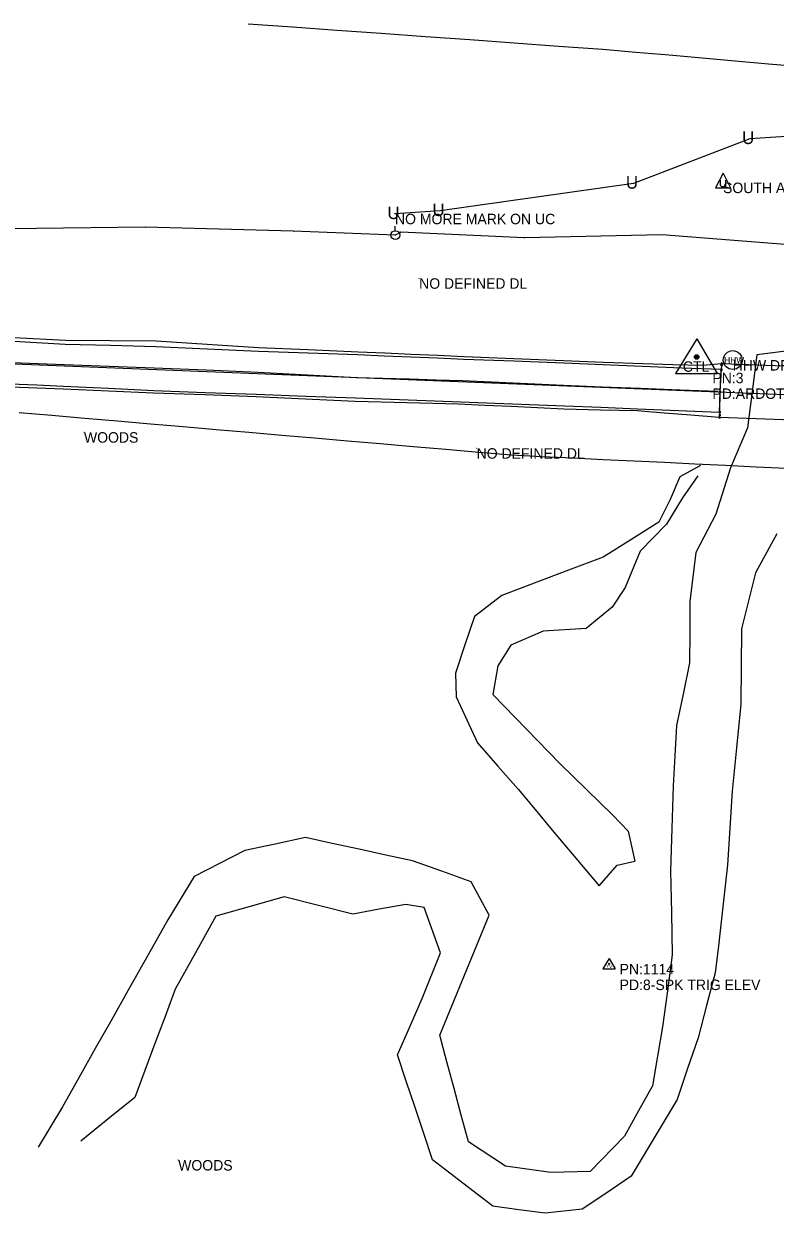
# Model space of a CAD drawing. Extents: x 1138803 to 1169983, y 1655906 to 1658226.
# Drawn here: x 1141218 to 1141577, y 1657244 to 1657812 of the extents above; entities that cross this region are included whole.
import ezdxf

# ---------------------------------------------------------------- set-up
doc = ezdxf.new("R2010")
doc.units = 0
for name, color, linetype in [('Default', 7, 'Continuous'), ('S_BRIDGE', 7, 'Continuous'), ('S_DITCHLINE', 7, 'Continuous'), ('S_EDGE_PAVEMENT', 7, 'Continuous'), ('S_EXISTING_ALIGNMENT', 7, 'Continuous'), ('S_FIBER_OPTIC_CABLE', 7, 'Continuous'), ('S_HIST_HIGH_WATER', 7, 'Continuous'), ('S_HIST_HIGH_WATER_ANNOT', 7, 'Continuous'), ('S_MSC_PT_SYM', 7, 'Continuous'), ('S_PAVEMENT_CROWN', 7, 'Continuous'), ('S_PRIMARY_CTL', 7, 'Continuous'), ('S_PRIMARY_CTL_ANNOT', 7, 'Continuous'), ('S_SECONDARY_CTL', 7, 'Continuous'), ('S_SECONDARY_CTL_ANNOT', 7, 'Continuous'), ('S_SHOULDER', 7, 'Continuous'), ('S_STR_PT_SYM', 7, 'Continuous'), ('S_STREAM', 7, 'Continuous'), ('S_SURVEY_TEXT_ANNOT', 7, 'Continuous'), ('S_TREE', 7, 'Continuous'), ('S_UNDERGROUND_CABLE', 7, 'Continuous'), ('S_UTILITY_POLE', 7, 'Continuous'), ('S_UTILITY_POLE_ANNOT', 7, 'Continuous'), ('S_UTL_PT_SYM', 7, 'Continuous')]:
    doc.layers.add(name, color=color, linetype=linetype)

msp = doc.modelspace()

# ---------------------------------------------------------------- linework, layer by layer
at = {"layer": 'S_BRIDGE'}
for p, q in [((1141550.51, 1657636.42), (1141551.05, 1657647.03)), ((1141551.05, 1657647.03), (1141551.2, 1657649.23)), ((1141551.2, 1657649.23), (1141551.33, 1657650)), ((1141551.33, 1657650), (1141657.88, 1657645.9)), ((1141550.32, 1657626.72), (1141550.51, 1657636.42)), ((1141550.22, 1657624.21), (1141550.27, 1657625.35)), ((1141656.97, 1657620.11), (1141550.22, 1657624.21)), ((1141550.27, 1657625.35), (1141550.32, 1657626.72))]:
    msp.add_line(p, q, dxfattribs=at)
at = {"layer": 'S_DITCHLINE'}
for points in [[(1141541.04, 1657601.27), (1141531.25, 1657595.88), (1141526.63, 1657585.07), (1141521.22, 1657574.19), (1141507.88, 1657565.88), (1141494.54, 1657557.57), (1141478.07, 1657551.36), (1141461.6, 1657545.15), (1141446.26, 1657539.17), (1141433.2, 1657529.16), (1141428.61, 1657515.63), (1141424.02, 1657502.1), (1141424.42, 1657490.82), (1141434.58, 1657468.85), (1141444.28, 1657457.86), (1141453.98, 1657446.86), (1141462.12, 1657437.05), (1141470.25, 1657427.24), (1141481.5, 1657413.95), (1141492.75, 1657400.66), (1141501.28, 1657410.54), (1141509.7, 1657412.4)], [(1141539.75, 1657596.34), (1141532.41, 1657585.9), (1141524.85, 1657573.36), (1141512.28, 1657560.34), (1141505.08, 1657543.03), (1141498.82, 1657533.6), (1141486.53, 1657523.47), (1141465.99, 1657522.16), (1141450.49, 1657515.58), (1141444.25, 1657505.75), (1141441.92, 1657491.99), (1141457.97, 1657475.42), (1141474.02, 1657458.85), (1141486.63, 1657446.6), (1141499.23, 1657434.34), (1141506.52, 1657426.83), (1141509.71, 1657412.45)]]:
    msp.add_lwpolyline(points, dxfattribs=at)
at = {"layer": 'S_EDGE_PAVEMENT'}
for points in [[(1141550.85, 1657647.04), (1141532.15, 1657647.74), (1141513.44, 1657648.45), (1141494.6, 1657649.28), (1141475.75, 1657650.11), (1141451.94, 1657651.01), (1141428.12, 1657651.91), (1141415.44, 1657652.45), (1141402.76, 1657652.98), (1141390.08, 1657653.52), (1141377.4, 1657654.06), (1141353.66, 1657654.85), (1141329.92, 1657655.65), (1141305.44, 1657656.78), (1141280.95, 1657657.91), (1141259.32, 1657658.49), (1141237.68, 1657659.07), (1141213.11, 1657660.44)], [(1141550.85, 1657647.04), (1141550.33, 1657636.66), (1141550.03, 1657626.61), (1141530.53, 1657627.42), (1141511.03, 1657628.23), (1141493.55, 1657628.95), (1141476.07, 1657629.67), (1141451.31, 1657630.56), (1141426.54, 1657631.46), (1141413.99, 1657631.95), (1141401.44, 1657632.44), (1141388.89, 1657632.94), (1141376.34, 1657633.43), (1141352.59, 1657634.27), (1141328.84, 1657635.11), (1141304.45, 1657636.02), (1141280.05, 1657636.93), (1141258.42, 1657638), (1141236.8, 1657639.06), (1141224.13, 1657639.55), (1141211.47, 1657640.03)]]:
    msp.add_lwpolyline(points, dxfattribs=at)
at = {"layer": 'S_EXISTING_ALIGNMENT'}
msp.add_line((1140481.53, 1657679.14), (1142022.15, 1657617.46), dxfattribs=at)
at = {"layer": 'S_FIBER_OPTIC_CABLE'}
for p, q in [((1141275.94, 1657715.01), (1141210.99, 1657714.26)), ((1141346.62, 1657713.17), (1141275.94, 1657715.01)), ((1141395.33, 1657711.21), (1141346.62, 1657713.17)), ((1141397.9, 1657712.62), (1141395.33, 1657711.21)), ((1141457.09, 1657709.94), (1141397.9, 1657712.62)), ((1141522.77, 1657711.39), (1141457.09, 1657709.94)), ((1141628.93, 1657703.02), (1141522.77, 1657711.39))]:
    msp.add_line(p, q, dxfattribs=at)
at = {"layer": 'S_HIST_HIGH_WATER'}
msp.add_circle((1141556.45, 1657651.6), 4.5, dxfattribs=at)
at = {"layer": 'S_MSC_PT_SYM'}
for points in [[(1141395.17, 1657721.42), (1141395.17, 1657721.47), (1141395.17, 1657721.42), (1141395.12, 1657721.42), (1141395.17, 1657721.42), (1141395.17, 1657721.37), (1141395.17, 1657721.42), (1141395.22, 1657721.42)], [(1141406.72, 1657690.63), (1141406.72, 1657690.68), (1141406.72, 1657690.63), (1141406.67, 1657690.63), (1141406.72, 1657690.63), (1141406.72, 1657690.58), (1141406.72, 1657690.63), (1141406.77, 1657690.63)], [(1141246.64, 1657617.17), (1141246.64, 1657617.22), (1141246.64, 1657617.17), (1141246.59, 1657617.17), (1141246.64, 1657617.17), (1141246.64, 1657617.12), (1141246.64, 1657617.17), (1141246.69, 1657617.17)], [(1141434.17, 1657609.53), (1141434.17, 1657609.58), (1141434.17, 1657609.53), (1141434.12, 1657609.53), (1141434.17, 1657609.53), (1141434.17, 1657609.48), (1141434.17, 1657609.53), (1141434.22, 1657609.53)], [(1141291.64, 1657269.82), (1141291.64, 1657269.87), (1141291.64, 1657269.82), (1141291.59, 1657269.82), (1141291.64, 1657269.82), (1141291.64, 1657269.77), (1141291.64, 1657269.82), (1141291.69, 1657269.82)]]:
    msp.add_lwpolyline(points, dxfattribs=at)
at = {"layer": 'S_PAVEMENT_CROWN'}
msp.add_lwpolyline([(1141549.45, 1657636.6), (1141531.28, 1657637.31), (1141512.38, 1657638.04), (1141494, 1657638.73), (1141475.62, 1657639.42), (1141451.54, 1657640.54), (1141427.46, 1657641.65), (1141414.78, 1657642.04), (1141402.11, 1657642.42), (1141389.44, 1657642.8), (1141376.77, 1657643.18), (1141353.34, 1657644.42), (1141329.91, 1657645.66), (1141305.07, 1657646.7), (1141280.23, 1657647.74), (1141258.68, 1657648.53), (1141237.14, 1657649.33), (1141212.32, 1657650.33)], dxfattribs=at)
at = {"layer": 'S_PRIMARY_CTL'}
for p, q in [((1141539.25, 1657661.76), (1141529.21, 1657645.25)), ((1141539.25, 1657661.76), (1141549.07, 1657645.25)), ((1141529.21, 1657645.25), (1141549.07, 1657645.25))]:
    msp.add_line(p, q, dxfattribs=at)
for radius in [1.04, 0.609, 0.344]:
    msp.add_circle((1141539.25, 1657653.06), radius, dxfattribs=at)
at = {"layer": 'S_SECONDARY_CTL'}
for p, q in [((1141497.46, 1657366.05), (1141494.45, 1657361.1)), ((1141497.46, 1657366.05), (1141500.4, 1657361.1)), ((1141494.45, 1657361.1), (1141500.4, 1657361.1))]:
    msp.add_line(p, q, dxfattribs=at)
for radius in [0.311, 0.183, 0.103]:
    msp.add_circle((1141497.46, 1657363.44), radius, dxfattribs=at)
at = {"layer": 'S_SHOULDER'}
for points in [[(1141551.28, 1657649.82), (1141542.03, 1657648.94), (1141527.89, 1657649.37), (1141513.74, 1657649.8), (1141494.74, 1657650.5), (1141475.73, 1657651.2), (1141452, 1657652.17), (1141428.27, 1657653.15), (1141415.61, 1657653.71), (1141402.94, 1657654.27), (1141390.28, 1657654.83), (1141377.62, 1657655.4), (1141353.78, 1657656.43), (1141329.94, 1657657.45), (1141305.51, 1657659.04), (1141281.08, 1657660.62), (1141259.48, 1657660.76), (1141237.88, 1657660.9), (1141213.1, 1657662.14)], [(1141550.2, 1657626.27), (1141550.02, 1657625.04), (1141550.04, 1657624.21), (1141536.51, 1657625.26), (1141523.67, 1657626.28), (1141510.84, 1657627.3), (1141493.35, 1657627.74), (1141475.86, 1657628.19), (1141463.29, 1657628.78), (1141450.72, 1657629.37), (1141438.15, 1657629.96), (1141425.58, 1657630.56), (1141400.86, 1657631.18), (1141376.14, 1657631.79), (1141352.52, 1657632.91), (1141328.89, 1657634.03), (1141304.37, 1657634.93), (1141279.86, 1657635.83), (1141258.38, 1657636.77), (1141236.89, 1657637.71), (1141224.31, 1657638.17), (1141211.72, 1657638.64)]]:
    msp.add_lwpolyline(points, dxfattribs=at)
at = {"layer": 'S_STR_PT_SYM'}
for points in [[(1141551.05, 1657647.03), (1141551.05, 1657647.53), (1141551.05, 1657647.03), (1141550.55, 1657647.03), (1141551.05, 1657647.03), (1141551.05, 1657646.53), (1141551.05, 1657647.03), (1141551.55, 1657647.03)], [(1141551.2, 1657649.23), (1141551.2, 1657649.73), (1141551.2, 1657649.23), (1141550.7, 1657649.23), (1141551.2, 1657649.23), (1141551.2, 1657648.73), (1141551.2, 1657649.23), (1141551.7, 1657649.23)], [(1141551.33, 1657650), (1141551.33, 1657650.5), (1141551.33, 1657650), (1141550.83, 1657650), (1141551.33, 1657650), (1141551.33, 1657649.5), (1141551.33, 1657650), (1141551.83, 1657650)], [(1141550.51, 1657636.42), (1141550.51, 1657636.92), (1141550.51, 1657636.42), (1141550.01, 1657636.42), (1141550.51, 1657636.42), (1141550.51, 1657635.92), (1141550.51, 1657636.42), (1141551.01, 1657636.42)], [(1141550.22, 1657624.21), (1141550.22, 1657624.71), (1141550.22, 1657624.21), (1141549.72, 1657624.21), (1141550.22, 1657624.21), (1141550.22, 1657623.71), (1141550.22, 1657624.21), (1141550.72, 1657624.21)], [(1141550.27, 1657625.35), (1141550.27, 1657625.85), (1141550.27, 1657625.35), (1141549.77, 1657625.35), (1141550.27, 1657625.35), (1141550.27, 1657624.85), (1141550.27, 1657625.35), (1141550.77, 1657625.35)], [(1141550.32, 1657626.72), (1141550.32, 1657627.22), (1141550.32, 1657626.72), (1141549.82, 1657626.72), (1141550.32, 1657626.72), (1141550.32, 1657626.22), (1141550.32, 1657626.72), (1141550.82, 1657626.72)]]:
    msp.add_lwpolyline(points, dxfattribs=at)
at = {"layer": 'S_STREAM'}
for points in [[(1141585.68, 1657656.36), (1141567.92, 1657654.08), (1141565.73, 1657636.63), (1141563.55, 1657619.19), (1141555.43, 1657600.21), (1141548.34, 1657578.06), (1141538.92, 1657559.7), (1141535.99, 1657536.37), (1141535.91, 1657521.7), (1141535.82, 1657507.04), (1141532.73, 1657492.13), (1141529.64, 1657477.21), (1141528.82, 1657462.79), (1141528.01, 1657448.38), (1141527.39, 1657428.12), (1141526.78, 1657407.86), (1141527.2, 1657387.83), (1141527.62, 1657367.79), (1141525.3, 1657350.58), (1141522.97, 1657333.37), (1141520.57, 1657319.34), (1141518.16, 1657305.31), (1141511.47, 1657293.23), (1141504.77, 1657281.15), (1141488.44, 1657264.29), (1141469.54, 1657263.94), (1141447.99, 1657266.92), (1141430.26, 1657278.56), (1141426.84, 1657291.26), (1141423.42, 1657303.97), (1141420.01, 1657316.67), (1141416.59, 1657329.37), (1141422.49, 1657343.68), (1141428.4, 1657357.99), (1141434.3, 1657372.3), (1141440.21, 1657386.61), (1141431.63, 1657402.67), (1141417.59, 1657407.61), (1141403.56, 1657412.55), (1141390.79, 1657415.33), (1141378.02, 1657418.11), (1141365.25, 1657420.89), (1141352.48, 1657423.67), (1141337.96, 1657420.63), (1141323.44, 1657417.58), (1141311.32, 1657411.36), (1141299.21, 1657405.13), (1141286.75, 1657384.46), (1141277.25, 1657367.68), (1141267.75, 1657350.89), (1141259.89, 1657336.95), (1141252.04, 1657323.02), (1141244.18, 1657309.08), (1141236.33, 1657295.14), (1141224.75, 1657275.9)], [(1141577.5, 1657568.72), (1141567.3, 1657550.04), (1141564.01, 1657536.66), (1141560.72, 1657523.29), (1141560.54, 1657505.35), (1141560.37, 1657487.41), (1141558.27, 1657466.6), (1141556.17, 1657445.79), (1141555.08, 1657428.26), (1141553.99, 1657410.74), (1141552.53, 1657397.85), (1141551.07, 1657384.95), (1141549.61, 1657372.06), (1141548.15, 1657359.16), (1141544.02, 1657343.64), (1141539.89, 1657328.13), (1141534.88, 1657313.44), (1141529.87, 1657298.76), (1141518.95, 1657280.43), (1141508.03, 1657262.09), (1141496.28, 1657254.22), (1141484.53, 1657246.34), (1141466.83, 1657244.45), (1141454.4, 1657246.11), (1141441.96, 1657247.77), (1141427.54, 1657258.86), (1141413.11, 1657269.94), (1141408.93, 1657282.45), (1141404.74, 1657294.97), (1141400.56, 1657307.48), (1141396.38, 1657319.99), (1141402.24, 1657333.47), (1141408.1, 1657346.95), (1141416.99, 1657368.74), (1141409.07, 1657390.33), (1141400.28, 1657391.82), (1141387.64, 1657389.49), (1141375.01, 1657387.16), (1141358.64, 1657391.32), (1141342.27, 1657395.49), (1141325.97, 1657390.85), (1141309.66, 1657386.21), (1141299.94, 1657368.77), (1141290.22, 1657351.32), (1141285.38, 1657338.4), (1141280.54, 1657325.48), (1141275.7, 1657312.56), (1141270.87, 1657299.63), (1141258.03, 1657289.26), (1141245.2, 1657278.88)]]:
    msp.add_lwpolyline(points, dxfattribs=at)
at = {"layer": 'S_TREE'}
for points in [[(1141325, 1657812.08), (1141346.17, 1657810.57), (1141367.34, 1657809.05), (1141388.52, 1657807.54), (1141409.69, 1657806.02), (1141430.86, 1657804.51), (1141452.03, 1657802.99), (1141473.2, 1657801.48), (1141494.37, 1657799.96), (1141510.2, 1657798.57), (1141526.04, 1657797.19), (1141541.87, 1657795.8), (1141557.7, 1657794.42), (1141573.53, 1657793.03), (1141589.37, 1657791.65)], [(1141215.64, 1657626.62), (1141231.32, 1657625.27), (1141247, 1657623.91), (1141262.68, 1657622.56), (1141278.36, 1657621.21), (1141294.04, 1657619.85), (1141309.73, 1657618.5), (1141325.41, 1657617.15), (1141341.09, 1657615.8), (1141356.77, 1657614.44), (1141372.45, 1657613.09), (1141388.13, 1657611.74), (1141403.81, 1657610.38), (1141419.49, 1657609.03), (1141435.18, 1657607.68), (1141450.86, 1657606.33), (1141465.45, 1657605.62), (1141480.04, 1657604.92), (1141494.63, 1657604.22), (1141509.23, 1657603.51), (1141523.82, 1657602.81), (1141538.41, 1657602.11), (1141553.01, 1657601.4), (1141567.6, 1657600.7), (1141582.19, 1657600)]]:
    msp.add_lwpolyline(points, dxfattribs=at)
at = {"layer": 'S_UNDERGROUND_CABLE'}
for p, q in [((1141617.98, 1657760.5), (1141564.59, 1657757.22)), ((1141564.59, 1657757.22), (1141509.11, 1657735.92)), ((1141551.85, 1657740.81), (1141548.32, 1657733.72)), ((1141550.65, 1657734.96), (1141550.65, 1657737.4)), ((1141551.85, 1657740.81), (1141555.34, 1657733.72)), ((1141553.01, 1657737.4), (1141553.01, 1657734.96)), ((1141509.11, 1657735.92), (1141416.73, 1657722.86)), ((1141548.32, 1657733.72), (1141555.34, 1657733.72)), ((1141551.27, 1657734.3), (1141550.65, 1657734.96)), ((1141552.47, 1657734.3), (1141551.27, 1657734.3)), ((1141553.01, 1657734.96), (1141552.47, 1657734.3)), ((1141416.73, 1657722.86), (1141395.19, 1657721.42))]:
    msp.add_line(p, q, dxfattribs=at)
at = {"layer": 'S_UTILITY_POLE'}
msp.add_line((1141395.21, 1657713.35), (1141395.21, 1657715.46), dxfattribs=at)
msp.add_circle((1141395.33, 1657711.21), 2.13, dxfattribs=at)
at = {"layer": 'S_UTL_PT_SYM'}
for points in [[(1141275.94, 1657715.01), (1141275.94, 1657715.06), (1141275.94, 1657715.01), (1141275.89, 1657715.01), (1141275.94, 1657715.01), (1141275.94, 1657714.96), (1141275.94, 1657715.01), (1141275.99, 1657715.01)], [(1141346.62, 1657713.17), (1141346.62, 1657713.22), (1141346.62, 1657713.17), (1141346.57, 1657713.17), (1141346.62, 1657713.17), (1141346.62, 1657713.12), (1141346.62, 1657713.17), (1141346.67, 1657713.17)], [(1141395.33, 1657711.21), (1141395.33, 1657711.26), (1141395.33, 1657711.21), (1141395.28, 1657711.21), (1141395.33, 1657711.21), (1141395.33, 1657711.16), (1141395.33, 1657711.21), (1141395.38, 1657711.21)], [(1141397.9, 1657712.62), (1141397.9, 1657712.67), (1141397.9, 1657712.62), (1141397.85, 1657712.62), (1141397.9, 1657712.62), (1141397.9, 1657712.57), (1141397.9, 1657712.62), (1141397.95, 1657712.62)], [(1141457.09, 1657709.94), (1141457.09, 1657709.99), (1141457.09, 1657709.94), (1141457.04, 1657709.94), (1141457.09, 1657709.94), (1141457.09, 1657709.89), (1141457.09, 1657709.94), (1141457.14, 1657709.94)], [(1141522.77, 1657711.39), (1141522.77, 1657711.44), (1141522.77, 1657711.39), (1141522.72, 1657711.39), (1141522.77, 1657711.39), (1141522.77, 1657711.34), (1141522.77, 1657711.39), (1141522.82, 1657711.39)]]:
    msp.add_lwpolyline(points, dxfattribs=at)

# ---------------------------------------------------------------- texts
at = {"layer": 'Default'}
for p in [(1141560.96, 1657754.68), (1141505.48, 1657733.37), (1141413.1, 1657720.31), (1141391.56, 1657718.88)]:
    msp.add_text('U', height=6, rotation=360, dxfattribs=at).set_placement(p)
at = {"layer": 'S_HIST_HIGH_WATER'}
msp.add_text('HHW', height=3, rotation=360, dxfattribs=at).set_placement((1141552.37, 1657650.1))
at = {"layer": 'S_HIST_HIGH_WATER_ANNOT'}
msp.add_text('HHW DRIFT AS GIVING BY AHTD IN  ELEV:204.56', height=5, dxfattribs=at).set_placement((1141556.45, 1657646.6))
at = {"layer": 'S_PRIMARY_CTL'}
msp.add_text('CTL', height=5, rotation=360, dxfattribs=at).set_placement((1141532.66, 1657645.99))
at = {"layer": 'S_PRIMARY_CTL_ANNOT'}
for s, p in [('PN:3', (1141546.75, 1657640.56)), ('PD:ARDOT STD. MON. STAMPED PN:3', (1141546.75, 1657633.06))]:
    msp.add_text(s, height=5, dxfattribs=at).set_placement(p)
at = {"layer": 'S_SECONDARY_CTL'}
msp.add_text('TV', height=1.5, rotation=360, dxfattribs=at).set_placement((1141496.25, 1657361.43))
at = {"layer": 'S_SECONDARY_CTL_ANNOT'}
for s, p in [('PN:1114', (1141502.46, 1657358.44)), ('PD:8-SPK TRIG ELEV', (1141502.46, 1657350.94))]:
    msp.add_text(s, height=5, dxfattribs=at).set_placement(p)
at = {"layer": 'S_SURVEY_TEXT_ANNOT'}
for s, p in [('NO MORE MARK ON UC', (1141395.17, 1657716.42)), ('NO DEFINED DL', (1141406.72, 1657685.63)), ('WOODS', (1141246.64, 1657612.17)), ('NO DEFINED DL', (1141434.17, 1657604.53)), ('WOODS', (1141291.64, 1657264.82))]:
    msp.add_text(s, height=5, dxfattribs=at).set_placement(p)
at = {"layer": 'S_UTILITY_POLE_ANNOT'}
msp.add_text('SOUTH ARK TELEPHONE', height=5, dxfattribs=at).set_placement((1141551.85, 1657731.28))

doc.saveas('drawing.dxf')
